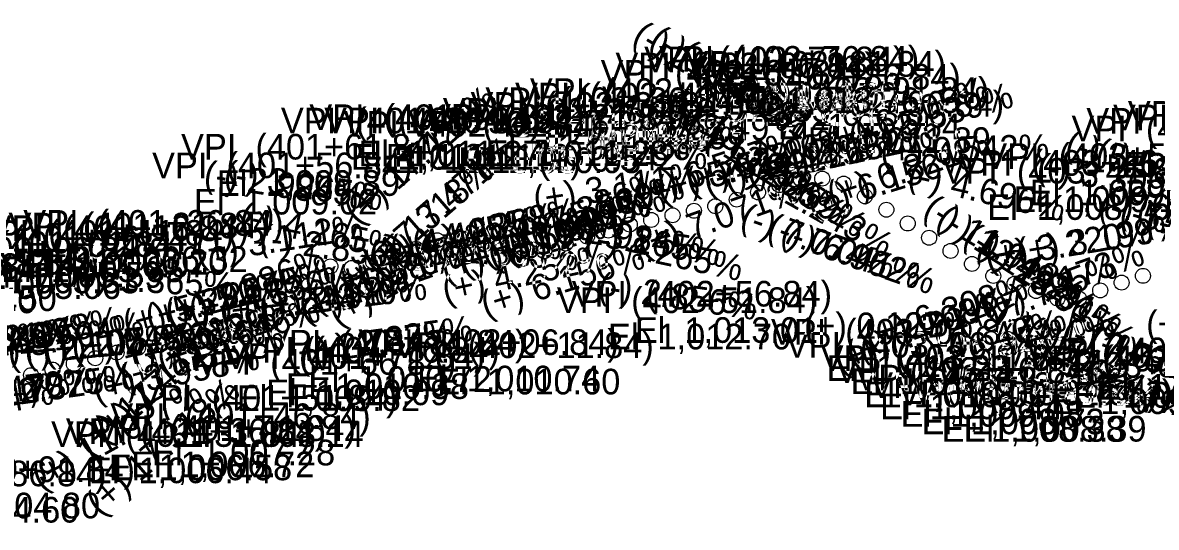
# Model space of a CAD drawing. Extents: x 16970812 to 16976737, y 12558429 to 12559451.
# Drawn here: x 16974482.8 to 16974747.9, y 12558927.7 to 12559045.8 of the extents above; entities that cross this region are included whole.
import ezdxf

# ---------------------------------------------------------------- set-up
doc = ezdxf.new("R2010")
doc.units = 0
doc.layers.add('RD_DDB_GradeTX', color=7, linetype='Continuous')
doc.layers.add('RD_DDB_PI', color=7, linetype='Continuous')

msp = doc.modelspace()

# ---------------------------------------------------------------- linework, layer by layer
at = {"layer": 'RD_DDB_PI'}
for centre in [(16974664.74, 12559009.16), (16974669.74, 12559009.29), (16974654.74, 12559006.07), (16974659.74, 12559007.77), (16974674.74, 12559008.12), (16974649.74, 12559004.36), (16974679.74, 12559005.13), (16974634.74, 12559000.7), (16974639.74, 12559001.76), (16974644.74, 12559002.83), (16974684.74, 12559002.01), (16974624.74, 12558998.52), (16974629.74, 12558999.62), (16974689.74, 12558998.79), (16974584.74, 12558995.64), (16974614.74, 12558995.71), (16974619.74, 12558997.12), (16974694.74, 12558995.45), (16974574.74, 12558992.89), (16974579.74, 12558994.86), (16974589.74, 12558994.9), (16974594.74, 12558994.08), (16974599.74, 12558993.01), (16974609.74, 12558994.07), (16974699.74, 12558992.37), (16974564.74, 12558989.78), (16974569.74, 12558991.23), (16974604.74, 12558992.3), (16974554.74, 12558988.75), (16974559.74, 12558988.4), (16974704.74, 12558989.31), (16974709.74, 12558986.5), (16974714.74, 12558984.73), (16974739.74, 12558984.96), (16974744.74, 12558986.54), (16974549.74, 12558984.39), (16974719.74, 12558982.97), (16974734.74, 12558983.13), (16974544.74, 12558980.02), (16974724.74, 12558981.23), (16974729.74, 12558981.26), (16974539.74, 12558975.69), (16974524.74, 12558971.53), (16974529.74, 12558972.22), (16974534.74, 12558972.92), (16974504.74, 12558968.58), (16974509.74, 12558969.66), (16974514.74, 12558970.29), (16974519.74, 12558970.92), (16974494.74, 12558965.95), (16974499.74, 12558967.27), (16974484.74, 12558963.3), (16974489.74, 12558964.63)]:
    msp.add_circle(centre, 1.75, dxfattribs=at)

# ---------------------------------------------------------------- texts
at = {"layer": 'RD_DDB_GradeTX'}
for s, rotation, p in [('(-) 11.948%', 329.1459, (16974624.97, 12559041.34)), ('(-) 12.492%', 328.0103, (16974628.9, 12559040.43)), ('(-) 12.881%', 327.216, (16974635.83, 12559037.08)), ('(-) 4.696%', 346.7874, (16974611.63, 12559026.02)), ('(+) 6.805%', 18.7912, (16974671.76, 12559015.03)), ('(+) 5.539%', 15.4802, (16974676.85, 12559015.62)), ('(+) 17.420%', 41.0557, (16974561.12, 12558998.28)), ('(-) 13.365%', 326.2467, (16974633.14, 12559025.78)), ('(-) 12.296%', 328.4176, (16974637.34, 12559020.17)), ('(+) 5.610%', 15.6682, (16974638.81, 12559005.59)), ('(-) 12.259%', 328.4937, (16974642.1, 12559017.14)), ('(+) 4.268%', 12.0469, (16974652.69, 12559007.59)), ('(+) 4.252%', 12.0011, (16974657.24, 12559008.55)), ('(+) 17.471%', 41.1393, (16974565.64, 12558986.32)), ('(+) 6.587%', 18.2285, (16974627.13, 12559002.95)), ('(+) 5.628%', 15.7166, (16974631.99, 12559003.68)), ('(+) 4.405%', 12.4204, (16974642.76, 12559005.56)), ('(+) 4.285%', 12.0923, (16974647.46, 12559006.49)), ('(+) 6.821%', 18.8307, (16974672.08, 12559002.47)), ('(+) 0.542%', 1.5531, (16974683.41, 12559012.66)), ('(-) 5.532%', 344.5396, (16974726.19, 12559014.9)), ('(-) 5.613%', 344.3231, (16974733.31, 12559013.16)), ('(+) 0.542%', 1.5531, (16974603.44, 12559010.49)), ('(-) 11.243%', 330.6573, (16974647.59, 12559011.11)), ('(+) 6.156%', 17.1077, (16974667.24, 12559000.33)), ('(-) 3.309%', 350.6045, (16974719.65, 12559009.41)), ('(-) 2.984%', 351.5129, (16974524.9, 12559007.6)), ('(-) 3.265%', 350.7273, (16974529.56, 12559007.76)), ('(+) 17.318%', 40.8895, (16974560.13, 12558981.44)), ('(+) 3.111%', 8.8408, (16974602.66, 12559001.47)), ('(-) 4.696%', 346.7874, (16974689.38, 12559007.76)), ('(+) 7.886%', 21.52, (16974596.1, 12558991.64)), ('(+) 5.539%', 15.4802, (16974599.93, 12558994.32)), ('(+) 7.071%', 19.4698, (16974627.77, 12558990.89)), ('(+) 4.268%', 12.0469, (16974574.56, 12558990.92)), ('(+) 6.646%', 18.3817, (16974591.05, 12558988.83)), ('(+) 6.821%', 18.8307, (16974592.76, 12558988.1)), ('(+) 6.805%', 18.7912, (16974596.29, 12558989.35)), ('(-) 11.948%', 329.1459, (16974692.94, 12559000.74)), ('(-) 5.737%', 343.9957, (16974733.98, 12559000.87)), ('(-) 5.690%', 344.1187, (16974738.91, 12558999.32)), ('(-) 4.265%', 347.9614, (16974533.2, 12558998)), ('(+) 4.405%', 12.4204, (16974564.75, 12558988.38)), ('(+) 4.285%', 12.0923, (16974569.34, 12558989.75)), ('(+) 5.796%', 16.1628, (16974585.89, 12558986.54)), ('(-) 7.074%', 340.5204, (16974650.18, 12558998.02)), ('(-) 12.492%', 328.0103, (16974695.99, 12558998.52)), ('(-) 5.615%', 344.3167, (16974745.24, 12558997.31)), ('(+) 3.111%', 8.8408, (16974523.67, 12558989.18)), ('(+) 11.077%', 28.98, (16974556.39, 12558974.63)), ('(+) 5.610%', 15.6682, (16974561.97, 12558984.03)), ('(+) 5.512%', 15.4095, (16974581.58, 12558985.09)), ('(-) 2.984%', 351.5129, (16974603.97, 12558995.81)), ('(-) 3.265%', 350.7273, (16974608.45, 12558994.88)), ('(-) 7.041%', 340.6064, (16974656.44, 12558995.71)), ('(-) 6.962%', 340.807, (16974659.56, 12558994.39)), ('(+) 3.220%', 9.1473, (16974708.34, 12558987.97)), ('(+) 3.199%', 9.0882, (16974715.67, 12558989.21)), ('(-) 2.856%', 351.8726, (16974537.89, 12558992.75)), ('(+) 5.628%', 15.7166, (16974555.17, 12558982.07)), ('(-) 4.265%', 347.9614, (16974613.83, 12558993.08)), ('(-) 12.881%', 327.216, (16974702.29, 12558994.28)), ('(+) 6.587%', 18.2285, (16974551.39, 12558978.01)), ('(-) 1.365%', 356.0945, (16974575.25, 12558990.35)), ('(-) 13.365%', 326.2467, (16974705.48, 12558991.87)), ('(+) 7.173%', 19.7305, (16974708.43, 12558976.02)), ('(+) 7.886%', 21.52, (16974517.62, 12558973.59)), ('(+) 7.071%', 19.4698, (16974548.63, 12558975.64)), ('(+) 4.252%', 12.0011, (16974581.59, 12558980.2)), ('(+) 6.156%', 17.1077, (16974591, 12558976.87)), ('(+) 7.705%', 21.07, (16974702.51, 12558972.26)), ('(-) 1.365%', 356.0945, (16974494.63, 12558983.83)), ('(+) 5.267%', 14.7548, (16974512.4, 12558973.71)), ('(+) 5.245%', 14.6942, (16974517.01, 12558974.9)), ('(+) 4.336%', 12.2337, (16974522.32, 12558975.46)), ('(+) 5.290%', 14.8148, (16974507.11, 12558972.33)), ('(+) 2.491%', 7.1005, (16974534.86, 12558975.82)), ('(+) 2.470%', 7.0402, (16974538.4, 12558976.24)), ('(-) 2.856%', 351.8726, (16974617.04, 12558981.45)), ('(+) 6.308%', 17.5064, (16974680.72, 12558969.49)), ('(+) 2.513%', 7.1606, (16974529.21, 12558975.13)), ('(+) 7.308%', 20.0734, (16974676.72, 12558965.12)), ('(+) 6.646%', 18.3817, (16974515.39, 12558963.69)), ('(+) 7.491%', 20.5323, (16974673.92, 12558963.56)), ('(-) 12.296%', 328.4176, (16974704.75, 12558978.73)), ('(+) 4.409%', 12.4309, (16974462.99, 12558964.28)), ('(+) 4.378%', 12.3465, (16974467.77, 12558965.3)), ('(+) 17.420%', 41.0557, (16974502.02, 12558946.8)), ('(+) 5.512%', 15.4095, (16974504.64, 12558963.88)), ('(+) 5.796%', 16.1628, (16974509.25, 12558964.33)), ('(+) 0.127%', 0.3642, (16974665.51, 12558971.85)), ('(+) 4.640%', 13.0615, (16974687.82, 12558964.09)), ('(+) 5.954%', 16.5775, (16974694.05, 12558961.73)), ('(+) 7.654%', 20.9421, (16974701.7, 12558959.25)), ('(-) 12.259%', 328.4937, (16974709.57, 12558975.79)), ('(+) 0.127%', 0.3642, (16974745.51, 12558972.36)), ('(+) 2.513%', 7.1606, (16974449.87, 12558965.17)), ('(+) 2.491%', 7.1005, (16974455.51, 12558965.94)), ('(+) 4.439%', 12.5145, (16974457.69, 12558963.13)), ('(+) 3.504%', 9.9364, (16974472.64, 12558965.56)), ('(+) 2.074%', 5.9202, (16974483.5, 12558965.74)), ('(+) 2.043%', 5.8332, (16974487.92, 12558966.17)), ('(+) 2.012%', 5.7458, (16974494.52, 12558966.81)), ('(+) 17.471%', 41.1393, (16974498.73, 12558943.81)), ('(+) 2.737%', 7.7918, (16974544.84, 12558965.2)), ('(+) 2.825%', 8.0388, (16974549.22, 12558965.88)), ('(-) 11.243%', 330.6573, (16974716.68, 12558972.27)), ('(-) 7.074%', 340.5204, (16974725.32, 12558971.44)), ('(+) 2.105%', 6.007, (16974479.61, 12558965.36)), ('(+) 5.312%', 14.874, (16974506.38, 12558959.74)), ('(-) 7.041%', 340.6064, (16974731.62, 12558969.24)), ('(-) 6.962%', 340.807, (16974734.83, 12558968.18)), ('(+) 3.958%', 11.1934, (16974499.83, 12558957.11)), ('(+) 2.470%', 7.0402, (16974460.51, 12558954.53)), ('(+) 2.737%', 7.7918, (16974465.63, 12558954.36)), ('(+) 2.825%', 8.0388, (16974470.06, 12558954.7)), ('(+) 3.914%', 11.0723, (16974451.68, 12558949.1)), ('(+) 4.470%', 12.5977, (16974455.76, 12558950.43)), ('(+) 17.318%', 40.8895, (16974500.87, 12558930.13)), ('(+) 11.077%', 28.98, (16974487.03, 12558936.21))]:
    msp.add_text(s, height=6, rotation=rotation, dxfattribs=at).set_placement(p)
at = {"layer": 'RD_DDB_PI'}
for s, p in [('VPI  (402+71.84)', (16974628.1, 12559034.16)), ('VPI  (402+76.84)', (16974631.56, 12559034.29)), ('VPI  (402+81.84)', (16974637.8, 12559033.12)), ('VPI  (402+61.84)', (16974617.92, 12559031.07)), ('VPI  (402+66.84)', (16974621.39, 12559032.77)), ('VPI  (402+86.84)', (16974641.27, 12559030.13)), ('VPI  (402+41.84)', (16974597.92, 12559025.7)), ('VPI  (402+46.84)', (16974601.39, 12559026.76)), ('El  1,013.97', (16974639.7, 12559025.66)), ('El  1,014.00', (16974644.7, 12559025.79)), ('VPI  (402+91.84)', (16974647.92, 12559027.01)), ('VPI  (402+31.84)', (16974587.51, 12559023.52)), ('VPI  (402+36.84)', (16974590.97, 12559024.62)), ('El  1,013.35', (16974628.9, 12559022.57)), ('El  1,013.69', (16974634.52, 12559024.27)), ('El  1,013.76', (16974649.7, 12559024.62)), ('VPI  (402+96.84)', (16974651.39, 12559023.79)), ('VPI  (401+86.84)', (16974543.16, 12559019.86)), ('VPI  (401+91.84)', (16974549.81, 12559020.64)), ('VPI  (401+96.84)', (16974553.27, 12559019.9)), ('VPI  (402+21.84)', (16974577.57, 12559020.71)), ('VPI  (402+26.84)', (16974581.03, 12559022.12)), ('El  1,013.16', (16974656.06, 12559021.63)), ('VPI  (403+76.84)', (16974731.5, 12559019.82)), ('VPI  (403+81.84)', (16974737.74, 12559020.62)), ('VPI  (403+86.84)', (16974741.21, 12559021.42)), ('VPI  (402+01.84)', (16974557.8, 12559019.08)), ('VPI  (402+16.84)', (16974572.92, 12559019.07)), ('El  1,012.28', (16974609.14, 12559017.2)), ('El  1,012.49', (16974614.58, 12559018.26)), ('El  1,012.54', (16974659.35, 12559018.51)), ('VPI  (403+71.84)', (16974728.04, 12559018.02)), ('El  1,011.84', (16974601.36, 12559015.02)), ('El  1,012.06', (16974604.47, 12559016.12)), ('El  1,011.89', (16974666.36, 12559015.29)), ('VPI  (401+61.84)', (16974519.81, 12559013.75)), ('El  1,011.27', (16974561.3, 12559012.14)), ('El  1,011.28', (16974591.03, 12559012.21)), ('El  1,011.56', (16974596.24, 12559013.62)), ('VPI  (401+56.84)', (16974513.04, 12559009.39)), ('El  1,011.11', (16974559.54, 12559011.36)), ('El  1,011.12', (16974567.68, 12559011.4)), ('El  1,010.95', (16974569.61, 12559010.58)), ('El  1,010.95', (16974584.61, 12559010.57)), ('VPI  (403+46.84)', (16974701.33, 12559009.96)), ('VPI  (403+51.84)', (16974707.63, 12559011.54)), ('El  1,010.74', (16974740, 12559009.52)), ('VPI  (403+41.84)', (16974697.86, 12559008.13)), ('El  1,009.89', (16974528.17, 12559005.25)), ('El  1,009.13', (16974714.44, 12559001.46)), ('El  1,009.44', (16974718.28, 12559003.04)), ('El  1,009.02', (16974522.84, 12559000.89)), ('El  1,008.76', (16974708.34, 12558999.63)), ('VPI  (401+26.84)', (16974482.92, 12558995.92)), ('VPI  (401+11.84)', (16974471.35, 12558993.58)), ('VPI  (401+16.84)', (16974474.81, 12558994.66)), ('VPI  (401+21.84)', (16974479.46, 12558995.29)), ('VPI  (401+01.84)', (16974459.69, 12558990.95)), ('VPI  (401+06.84)', (16974463.16, 12558992.27)), ('VPI  (400+96.84)', (16974451.62, 12558989.63)), ('VPI  (400+71.84)', (16974428.33, 12558985.78)), ('VPI  (400+76.84)', (16974431.8, 12558986.3)), ('VPI  (400+81.84)', (16974438.04, 12558986.81)), ('El  1,006.07', (16974483.34, 12558986.16)), ('El  1,006.20', (16974487.81, 12558986.79)), ('El  1,006.32', (16974492.55, 12558987.42)), ('El  1,005.59', (16974472.81, 12558983.77)), ('El  1,005.85', (16974477.72, 12558985.08)), ('El  1,005.06', (16974462.93, 12558981.13)), ('El  1,005.33', (16974467.25, 12558982.45)), ('El  1,004.40', (16974443.17, 12558977.8)), ('El  1,004.50', (16974447.93, 12558978.31)), ('VPI  (402+51.84)', (16974607.68, 12558977.83)), ('VPI  (402+56.84)', (16974611.15, 12558979.36)), ('El  1,012.70', (16974619.64, 12558969.33)), ('El  1,013.01', (16974625.94, 12558970.86)), ('VPI  (403+01.84)', (16974657.74, 12558970.45)), ('VPI  (401+81.84)', (16974539.69, 12558967.89)), ('VPI  (402+06.84)', (16974561.27, 12558968.01)), ('VPI  (402+11.84)', (16974569.46, 12558967.3)), ('VPI  (403+06.84)', (16974661.21, 12558967.37)), ('VPI  (401+71.84)', (16974529.99, 12558964.78)), ('VPI  (401+76.84)', (16974533.45, 12558966.23)), ('VPI  (403+11.84)', (16974669.4, 12558964.31)), ('VPI  (403+61.84)', (16974717.86, 12558964.18)), ('VPI  (403+66.84)', (16974721.33, 12558966.1)), ('VPI  (401+66.84)', (16974523.27, 12558963.4)), ('El  1,011.23', (16974670.74, 12558961.95)), ('VPI  (403+16.84)', (16974672.86, 12558961.5)), ('VPI  (403+56.84)', (16974711.09, 12558962.7)), ('El  1,010.72', (16974549.67, 12558959.39)), ('El  1,010.74', (16974575, 12558959.51)), ('El  1,010.60', (16974579.7, 12558958.8)), ('El  1,010.61', (16974676.36, 12558958.87)), ('VPI  (403+21.84)', (16974677.51, 12558959.73)), ('El  1,010.09', (16974539.7, 12558956.28)), ('El  1,010.38', (16974544.32, 12558957.73)), ('VPI  (403+26.84)', (16974680.97, 12558957.97)), ('VPI  (403+31.84)', (16974687.45, 12558956.23)), ('VPI  (403+36.84)', (16974690.91, 12558956.26)), ('El  1,010.36', (16974734.41, 12558957.6)), ('VPI  (401+51.84)', (16974509.57, 12558955.02)), ('El  1,009.82', (16974532.84, 12558954.9)), ('El  1,010.00', (16974679.58, 12558955.81)), ('El  1,009.68', (16974723.2, 12558954.2)), ('El  1,009.97', (16974728.46, 12558955.68)), ('VPI  (401+46.84)', (16974503.27, 12558950.69)), ('El  1,009.44', (16974683.28, 12558953)), ('El  1,009.08', (16974688.08, 12558951.23)), ('El  1,008.73', (16974692.96, 12558949.47)), ('VPI  (401+31.84)', (16974489.4, 12558946.53)), ('VPI  (401+36.84)', (16974492.86, 12558947.22)), ('VPI  (401+41.84)', (16974499.81, 12558947.92)), ('El  1,008.14', (16974519.7, 12558946.52)), ('El  1,008.38', (16974697.66, 12558947.73)), ('El  1,008.39', (16974702.75, 12558947.76)), ('El  1,007.28', (16974513.02, 12558942.19)), ('VPI  (400+91.84)', (16974448.16, 12558938.3)), ('El  1,006.44', (16974498.28, 12558938.03)), ('El  1,006.58', (16974502.96, 12558938.72)), ('El  1,006.72', (16974508.14, 12558939.42)), ('VPI  (400+86.84)', (16974441.5, 12558937.31)), ('El  1,004.80', (16974458.05, 12558929.8)), ('El  1,004.60', (16974453.17, 12558928.81))]:
    msp.add_text(s, height=6, dxfattribs=at).set_placement(p)

doc.saveas('drawing.dxf')
